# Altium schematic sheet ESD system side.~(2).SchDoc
size A3; SheetNumber: 11; SheetTotal: 11
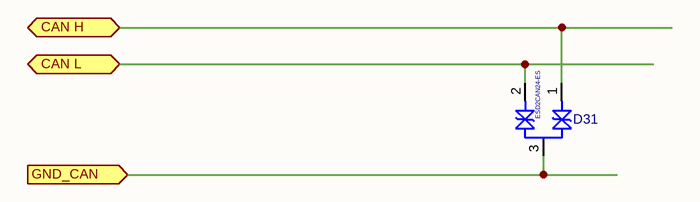
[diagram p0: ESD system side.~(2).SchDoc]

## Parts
D31  ESD2CAN24-ES  [SOT-23 123]

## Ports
CAN H (bidir, see Arhitecture[6B], BMS[8B], MCU[8A]), CAN L (bidir, see Arhitecture[6B], BMS[8B], MCU[8B]), GND_CAN

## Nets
CAN H: D31.1 ; port CAN H
CAN L: D31.2 ; port CAN L
GND_CAN: D31.3 ; port GND_CAN

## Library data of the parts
D31 = ESD2CAN24-ES: ESD TVS CAN; Manufacturer: ElecSuper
